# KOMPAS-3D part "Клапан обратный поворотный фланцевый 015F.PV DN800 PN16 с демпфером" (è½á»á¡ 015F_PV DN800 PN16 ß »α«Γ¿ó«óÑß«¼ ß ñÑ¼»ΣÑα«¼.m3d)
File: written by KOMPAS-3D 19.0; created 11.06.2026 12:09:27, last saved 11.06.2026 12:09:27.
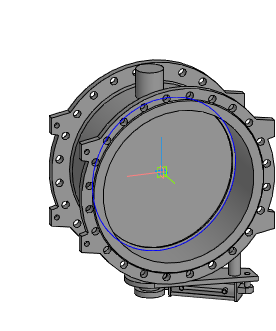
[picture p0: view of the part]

Document properties: Автор: Энергия; Полное имя файла: Z:\3.Личные\kachalov\001_3d для проектировщиков\5.5 Тип 015F.PV Клапан обратный поворотный с двумя эксцентриками\_stp_Клапан 015F.PV DN300-DN1200 с противовесом с демпфером\Клапан 015F_PV DN800 PN16 с противовесом с демпфером.m3d

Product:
- Part/product: Клапан обратный поворотный фланцевый 015F.PV DN800 PN16 с демпфером

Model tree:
1. Операция без истории:1
2. Сплайн:1
     Координата Y = 30; Координата Z = 400; Вес = 1; Координата X = 800; Координата Y = 135.322; Координата Z = 400; Вес = 0.333333; Координата X = 800; Координата Y = 135.322; Координата Z = -400; Вес = 0.333333; Координата Y = 30; Координата Z = -400; Вес = 1; Координата X = -800; Координата Y = -75.322; Координата Z = -400; Вес = 0.333333; Координата X = -800; Координата Y = -75.322; Координата Z = 400; Вес = 0.333333; Порядок = 4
